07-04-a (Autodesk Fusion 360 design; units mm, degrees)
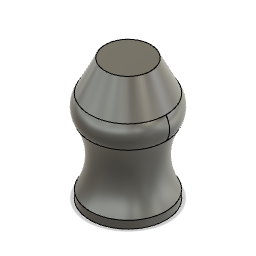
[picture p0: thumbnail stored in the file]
sketch "スケッチ1" plane through (0, 0, 0) normal (0, 1, 0) x axis (1, 0, 0)
  circle C1 centre (0, 0) radius 25
  point P1 (0, 0)
  point P2 (0, 0)
  coincident P1 P2
  dimension "d1" diameter C1 = 50
extrude "押し出し" new body sketch "スケッチ1" along normal blind 5
work_plane "作業平面1" AlongDistance 20
sketch "スケッチ2" plane through (0, 25, 0) normal (0, 1, 0) x axis (1, 0, 0)
  circle C1 centre (0, 0) radius 20
  point P1 (0, 0)
  point P2 (0, 0)
  coincident P1 P2
  dimension "d5" diameter C1 = 40
work_plane "作業平面2" AlongDistance 20
sketch "スケッチ3" plane through (0, 45, 0) normal (0, 1, 0) x axis (1, 0, 0)
  circle C1 centre (0, 0) radius 25
loft "ロフト1" sketch "スケッチ2" + "スケッチ3"
work_plane "作業平面3" AlongDistance 15
sketch "スケッチ4" plane through (0, 60, 0) normal (0, 1, 0) x axis (1, 0, 0)
  circle C1 centre (0, 0) radius 25
sketch "スケッチ5" plane through (0, 0, 0) normal (0, 0, 1) x axis (1, 0, 0)
  line L1 (-25, 60) -> (25, 60)
  line L2 (25, 45) -> (-25, 45)
  arc A1 centre (-14.3816, 52.5) radius 13 clockwise from (-25, 45) to (-25, 60)
  arc A2 centre (14.3816, 52.5) radius 13 clockwise from (25, 60) to (25, 45)
  point P2 (-25, 60)
  point P9 (-25, 60)
  point P3 (-25, 45)
  point P10 (-25, 45)
  point P5 (25, 60)
  point P8 (25, 60)
  point P6 (25, 45)
  point P11 (25, 45)
  coincident P2 P9
  coincident P3 P10
  coincident P5 P8
  coincident P6 P11
  equal A1 A2
  dimension "d8" radius A1 = 13
sketch "スケッチ6" plane through (0, 0, 0) normal (1, 0, 0) x axis (0, 0, -1)
  line L1 (-25, 60) -> (25, 60)
  line L2 (25, 45) -> (-25, 45)
  arc A1 centre (-14.3816, 52.5) radius 13 clockwise from (-25, 45) to (-25, 60)
  arc A2 centre (14.3816, 52.5) radius 13 clockwise from (25, 60) to (25, 45)
  point P2 (-25, 60)
  point P9 (-25, 60)
  point P3 (-25, 45)
  point P10 (-25, 45)
  point P6 (25, 45)
  point P11 (25, 45)
  point P5 (25, 60)
  point P8 (25, 60)
  coincident P2 P9
  coincident P3 P10
  coincident P6 P11
  coincident P5 P8
  equal A1 A2
  dimension "d9" radius A1 = 13
loft "ロフト2" sketch "スケッチ4"
work_plane "作業平面4" AlongDistance 20
sketch "スケッチ7" plane through (0, 80, 0) normal (0, 1, 0) x axis (1, 0, 0)
  circle C1 centre (0, 0) radius 15
  point P1 (0, 0)
  point P2 (0, 0)
  coincident P1 P2
  dimension "d12" diameter C1 = 30
loft "ロフト3" sketch "スケッチ7"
